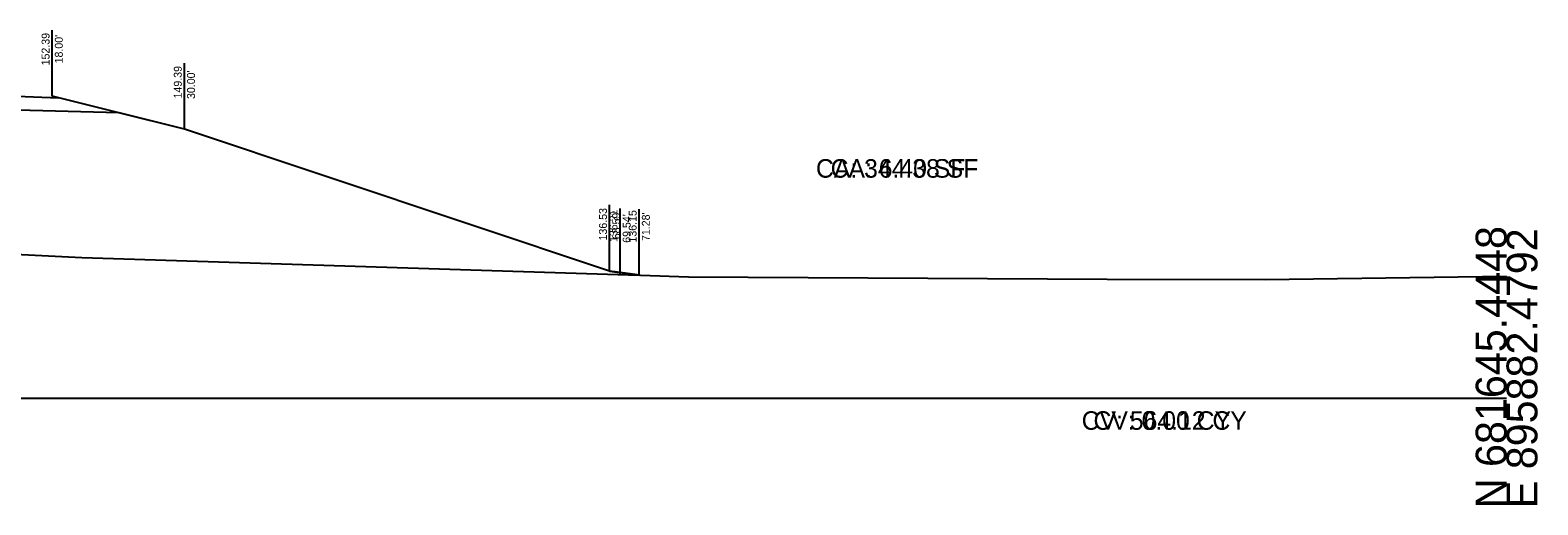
# Model space of a CAD drawing. Extents: x -100 to 7529, y -13 to 10775.
# Drawn here: x 3166 to 3302.8, y 5490.3 to 5533.4 of the extents above; entities that cross this region are included whole.
import ezdxf

# ---------------------------------------------------------------- set-up
doc = ezdxf.new("R2010")
doc.units = 0
for name, color, linetype in [('DTM_CONTOURS_MINOR', 7, 'Continuous'), ('DTM_X_GROUND', 7, 'Continuous'), ('X_PROFILES_1', 7, 'Continuous'), ('XS_CELL', 7, 'Continuous'), ('XS_M_SHAPES_EARTHWORK', 7, 'Continuous'), ('XS_P_TX_CLEARZONE', 7, 'Continuous'), ('XS_SHEET_EW_TX_AREA', 7, 'Continuous'), ('XS_SHEET_EW_TX_VOLUME', 7, 'Continuous')]:
    doc.layers.add(name, color=color, linetype=linetype)

msp = doc.modelspace()

# ---------------------------------------------------------------- linework, layer by layer
at = {"layer": 'DTM_X_GROUND'}
msp.add_line((3164, 5527.42), (3168.6, 5527.24), dxfattribs=at)
for points in [[(3218.58, 5511.53), (3180, 5524.39), (3180, 5524.39), (3180, 5524.39), (3168, 5527.39)], [(3218.58, 5511.53), (3220.68, 5511.23), (3220.69, 5511.23), (3221.39, 5511.15)], [(3221.39, 5511.15), (3225.75, 5511.01), (3263.76, 5510.78), (3278.1, 5510.76), (3300, 5511.07)]]:
    msp.add_lwpolyline(points, dxfattribs=at)
at = {"layer": 'XS_CELL'}
msp.add_line((3150, 5500), (3300, 5500), dxfattribs=at)
msp.add_line((3150, 5500), (3300, 5500), dxfattribs=at)
at = {"layer": 'XS_M_SHAPES_EARTHWORK'}
msp.add_lwpolyline([(3131.01, 5526.03), (3136.99, 5522.32), (3150, 5515.15), (3150, 5515.15), (3150.75, 5515.02), (3152.88, 5514.33), (3155.75, 5514.05), (3162.78, 5513.15), (3170.68, 5512.76), (3221.28, 5511.15), (3220.91, 5511.21), (3220.68, 5511.23), (3219.1, 5511.46), (3219.09, 5511.46), (3219.08, 5511.46), (3218.59, 5511.53), (3180, 5524.39), (3174.06, 5525.87), (3166, 5526.11), (3166, 5526.11), (3164, 5526.15), (3150, 5526.43), (3136, 5526.15), (3134, 5526.11)], close=True, dxfattribs=at)
at = {"layer": 'XS_P_TX_CLEARZONE'}
for p, q in [((3168, 5527.39), (3168, 5533.39)), ((3168, 5527.39), (3168, 5533.39)), ((3180, 5524.39), (3180, 5530.39)), ((3180, 5524.39), (3180, 5530.39)), ((3180, 5524.39), (3180, 5530.39)), ((3180, 5524.39), (3180, 5530.39)), ((3218.59, 5511.53), (3218.59, 5517.53)), ((3218.59, 5511.53), (3218.59, 5517.53)), ((3219.54, 5511.21), (3219.54, 5517.21)), ((3219.54, 5511.21), (3219.54, 5517.21)), ((3219.54, 5511.21), (3219.54, 5517.21)), ((3219.54, 5511.21), (3219.54, 5517.21)), ((3219.54, 5511.21), (3219.54, 5517.21)), ((3221.28, 5511.15), (3221.28, 5517.15)), ((3221.28, 5511.15), (3221.28, 5517.15)), ((3221.28, 5511.15), (3221.28, 5517.15))]:
    msp.add_line(p, q, dxfattribs=at)

# ---------------------------------------------------------------- texts
at = {"layer": 'DTM_CONTOURS_MINOR'}
msp.add_text('X', height=0.12, dxfattribs=at).set_placement((3219.5, 5511.15))
at = {"layer": 'X_PROFILES_1'}
for p in [(3218.55, 5511.47), (3219.5, 5511.15)]:
    msp.add_text('X', height=0.12, dxfattribs=at).set_placement(p)
at = {"layer": 'XS_CELL'}
for s, p in [('N 681645.4448', (3300, 5490)), ('N 681645.4448', (3300, 5490)), ('E 895882.4792', (3302.8, 5490)), ('E 895882.4792', (3302.8, 5490))]:
    msp.add_text(s, height=2.8, rotation=90, dxfattribs=at).set_placement(p)
at = {"layer": 'XS_P_TX_CLEARZONE'}
for s, p in [('152.39', (3167.76, 5530.19)), ('152.39', (3167.76, 5530.19)), ("18.00'", (3168.96, 5530.37)), ("18.00'", (3168.96, 5530.37)), ('149.39', (3179.76, 5527.19)), ('149.39', (3179.76, 5527.19)), ('149.39', (3179.76, 5527.19)), ('149.39', (3179.76, 5527.19)), ("30.00'", (3180.96, 5527.14)), ("30.00'", (3180.96, 5527.14)), ("30.00'", (3180.96, 5527.14)), ("30.00'", (3180.96, 5527.14)), ('136.53', (3218.35, 5514.3)), ('136.53', (3218.35, 5514.3)), ('136.21', (3219.3, 5514.16)), ('136.21', (3219.3, 5514.16)), ('136.21', (3219.3, 5514.16)), ('136.21', (3219.3, 5514.16)), ('136.21', (3219.3, 5514.16)), ("68.59'", (3219.55, 5514.41)), ("68.59'", (3219.55, 5514.41)), ("69.54'", (3220.5, 5514.09)), ("69.54'", (3220.5, 5514.09)), ("69.54'", (3220.5, 5514.09)), ("69.54'", (3220.5, 5514.09)), ("69.54'", (3220.5, 5514.09)), ('136.15', (3221.04, 5514.11)), ('136.15', (3221.04, 5514.11)), ('136.15', (3221.04, 5514.11)), ("71.28'", (3222.24, 5514.25)), ("71.28'", (3222.24, 5514.25)), ("71.28'", (3222.24, 5514.25))]:
    msp.add_text(s, height=0.72, rotation=90, dxfattribs=at).set_placement(p)
at = {"layer": 'XS_SHEET_EW_TX_AREA'}
for s, p in [('CA: 344.38 SF', (3237.32, 5520)), ('CA: 6.40 SF', (3238.65, 5520))]:
    msp.add_text(s, height=1.68, dxfattribs=at).set_placement(p)
at = {"layer": 'XS_SHEET_EW_TX_VOLUME'}
for s, p in [('CV: 564.12 CY', (3261.44, 5497.12)), ('CV: 0.00 CY', (3262.51, 5497.12))]:
    msp.add_text(s, height=1.68, dxfattribs=at).set_placement(p)

doc.saveas('drawing.dxf')
